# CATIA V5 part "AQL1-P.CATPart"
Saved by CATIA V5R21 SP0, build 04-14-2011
Part number: AQL1-P.SLDPRT
Bounding box of the stored display mesh (mm): x -0.689 to 0.811, y 0.802 to 2.702, z -1.283 to -0.493
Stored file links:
  C:\Users\user\Desktop\CATIA文件\0-最新文件\AQL1-P\AQL1-P.CATPart
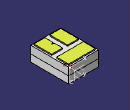
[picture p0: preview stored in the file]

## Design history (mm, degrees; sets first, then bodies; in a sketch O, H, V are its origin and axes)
AxisSystem1: origin (0.0609, 2.0131, -1.2826), X (-1, 0, 0), Y (0, 1, 0), Z (0, 0, -1)
Set1
  DatumSurface1 to DatumSurface14
  Line1: stored without definition
  Circle1: stored without definition
  Line2: stored without definition
  Circle2: stored without definition
  Line3: stored without definition
  Circle3: stored without definition
  Line4: stored without definition
  Circle4: stored without definition
  Line5: stored without definition
  Circle5: stored without definition
  Line6: stored without definition
  Circle6: stored without definition
  Line7: stored without definition
  Circle7: stored without definition
  Line8: stored without definition
  Circle8: stored without definition
  Line9 to Line20: stored without definition
  Circle9 to Circle16: stored without definition
  DatumSurface15 to DatumSurface20
  Line21 to Line32: stored without definition
  DatumSurface21 to DatumSurface26
  Line33 to Line44: stored without definition
  DatumSurface27 to DatumSurface35
  Line45 to Line65: stored without definition
  DatumSurface36 to DatumSurface43
  Line66 to Line83: stored without definition
  DatumSurface44 to DatumSurface51
  Line84 to Line101: stored without definition
  DatumSurface52 to DatumSurface57
  Line102 to Line113: stored without definition
  DatumSurface58 to DatumSurface67
  Line114 to Line137: stored without definition
  Point1 "发光中心（测试原点）": type Between, FirstPoint vertex [face of DatumSurface67], SecondPoint vertex [face of DatumSurface54], Ratio 0.5
  Point2 "几何中心": type Between, FirstPoint vertex [face of DatumSurface59], SecondPoint vertex [face of DatumSurface58], Ratio 0.5
  Point3 "虚拟坐标": (0.0058, -0.005, -0.0424), relative to Point1, in AxisSystem1
Body1 (main body)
